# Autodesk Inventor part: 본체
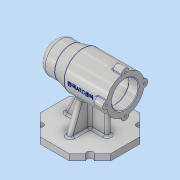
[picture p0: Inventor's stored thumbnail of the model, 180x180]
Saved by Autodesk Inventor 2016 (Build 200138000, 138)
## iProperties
Created: 2019-12
Part Number: 본체
Material: 알루미늄 6061
Document SubType Name: Modeling
Designer: 2-PC10
Density: 2.7 g/cm^3
Appearance: 알루미늄 - 평지
Mass: 724.914 g
Surface Area: 712.64 cm^2
Volume: 268.487 cm^3
Author: 2-PC10
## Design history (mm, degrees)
sketch "스케치1"
  geometry: L1 (0, 0)-(30, 0); L2 (0, 112)-(0, 0); L3 (0, 0)-(30, 0); L4 (30, 0)-(30, 67); L5 (30, 67)-(25, 87); L6 (25, 87)-(25, 112); L7 (25, 112)-(0, 112); L8 (21, 0)-(21, 15); L9 (21, 15)-(21, 15); L10 (24, 18)-(24, 66); L11 (21, 69)-(21, 69); L12 (21, 69)-(21, 80.7); L13 (20.7, 81)-(17.5, 81); L14 (17.5, 81)-(17.5, 98.7); L15 (17.2, 99)-(16, 99); L16 (16, 99)-(16, 102.7); L17 (15.7, 103)-(10.5, 103); L18 (10.5, 103)-(10.5, 103); L19 (7.5, 106)-(0, 106); L20 (21, 0)-(30, 0); A1 r 3 centre (7.5, 103) between (10.5, 103) and (7.5, 106); A2 r 0.3 centre (15.7, 102.7) between (16, 102.7) and (15.7, 103); A3 r 0.3 centre (17.2, 98.7) between (17.5, 98.7) and (17.2, 99); A4 r 0.3 centre (20.7, 80.7) between (21, 80.7) and (20.7, 81); A5 r 3 centre (21, 66) between (24, 66) and (21, 69); A6 r 3 centre (21, 18) between (21, 15) and (24, 18); 4 further points
  constraints: 40 end point, 12 perpendicular, 12 point on circle, 12 tangent, 10 point on line, 6 centre point, 3 equal radius, 3 horizontal, 1 collinear, 1 parallel
  dimensions: "d0" = 112 distance of L2.start L1.start; "d2" = 50 diameter of L6 L2; "d3" = 60 diameter of L4 L2; "d4" = 25 distance of L5.end L6.end; "d5" = 45 distance from line of L7 L4.end; "d7" = 15 distance of L8.start L8.end; "d8" = 54 distance of point (24, 15) point (24, 69); "d9" = 12 distance of L11.end point (21, 81); "d10" = 18 distance of L13.end point (17.5, 99); "d11" = 42 diameter of L8 L2; "d12" = 48 diameter of L10 L2; "d13" = 42 diameter of L12 L2; "d14" = 35 diameter of L14 L2; "d15" = 4 distance between parallel lines of L15 L17; "d16" = 32 diameter of L16 L2; "d17" = 21 diameter of L18 L2; "d18" = 3 distance between parallel lines of L17 L19; "d19" = 3 radius of A1; "d20" = 0.3 radius of A2; "d21" = 3 radius of A5
revolve "회전1" sketch "스케치1" stored, may be unused: angle "d22" = 90 deg
sketch "스케치2"
  geometry: C1 r 6 at (30, 0); 2 further points
  constraints: 1 centre point, 1 horizontal alignment, 1 other
  dimensions: "d23" = 12 diameter of C1
extrude "돌출1" join sketch "스케치2" distance "d24" = 16; taper "d25" = 0 deg
fillet "모깎기1" dims "d26" = 3
fillet "모깎기2" dims "d27" = 1
fillet "모깎기3" dims "d31" = 10
node "작업 평면1"
sketch "스케치3"
  geometry: L1 (6.771, 0)-(29.226, 0) reference; L2 (0, 8)-(0, -5.125); L3 (23.196, 0)-(-23.196, 0); L4 (-56, 32.804)-(-56, 79.196); L5 (-23.196, 112)-(23.196, 112); L6 (56, 79.196)-(56, 32.804); L7 (5.998, 0)-(-5.998, 0) reference; L8 (0, 56)-(67, -11); L9 (56, 32.804)-(43.134, 19.938); L10 (36.062, 12.866)-(23.196, 0); L11 (23.196, 112)-(36.062, 99.134); L12 (43.134, 92.062)-(56, 79.196); L13 (-56, 79.196)-(-43.134, 92.062); L14 (-36.062, 99.134)-(-23.196, 112); L15 (-23.196, 0)-(-36.062, 12.866); L16 (-43.134, 19.938)-(-56, 32.804); A1 r 5 centre (39.598, 16.402) between (43.134, 19.938) and (36.062, 12.866); A2 r 5 centre (39.598, 95.598) between (36.062, 99.134) and (43.134, 92.062); A3 r 5 centre (-39.598, 95.598) between (-43.134, 92.062) and (-36.062, 99.134); A4 r 5 centre (-39.598, 16.402) between (-36.062, 12.866) and (-43.134, 19.938); A5 r 56 centre (0, 56) between (35.908, 98.972) and (-39.598, 16.402); A6 r 56 centre (0, 56) between (-35.908, 13.028) and (42.972, 91.908); 2 further points
  constraints: 28 end point, 16 point on circle, 6 centre point, 2 midpoint, 1 coincident, 1 point on line, 1 vertical, 1 vertical alignment, 26 other
  dimensions: "d37" = 56 distance from line of L1 L8.start; "d40" = 10 diameter of A1; "d43" = 360 deg dimension on L8.start A1.centre (derived)
extrude "돌출2" join sketch "스케치3" distance "d38" = 10; taper "d39" = 0 deg
node "작업 평면2"
sketch "스케치4"
  geometry: L1 (-36, -70)-(-18.584, -22.151); L2 (-56, -80)-(-56, -70) reference; L3 (-56, -70)-(-43.134, -70) reference; L4 (0, 0)-(0, -47); L5 (36, -70)-(18.584, -22.151); L6 (-36.062, -80)-(-36.062, -70) reference; L7 (23.196, -70)-(36.062, -70) reference; L8 (-36.062, -70)-(36.062, -70); A1 r 28.915 centre (0, 0) between (-18.584, -22.151) and (18.584, -22.151); 3 further points
  constraints: 8 end point, 2 point on circle, 2 symmetric about line, 1 centre point, 1 coincident, 1 horizontal, 1 point on line, 1 vertical
  dimensions: "d46" = 20 distance from line of L1.start L2; "d47" = 110 deg angle of L1 L3; "d70" = 28.9147 radius of A1
extrude "돌출3" join sketch "스케치4" stored distance "d49" = 8; taper "d50" = 0 deg
sketch "스케치5"
  geometry: L1 (-70, 99.134)-(-70, 90.598) reference; L2 (-70, 94)-(-25.326, 73.168); L3 (-80, 112)-(-70, 112) reference; L4 (-70, 25)-(-26.997, 25); L5 (-80, 0)-(-70, 0) reference; L6 (-70, 25)-(-70, 94); L7 (-26.997, 25)-(-25.326, 73.168); 3 further points
  constraints: 8 end point, 1 collinear, 1 point on line
  dimensions: "d51" = 115 deg angle of L1 L2; "d52" = 18 distance from line of L2.start L3; "d53" = 25 distance between parallel lines of L4 L5; "d68" = 91.9869 deg angle of L4 L7; "d69" = 43.00307 distance of L4.start L4.end
extrude "돌출4" join sketch "스케치5" stored distance "d54" = 8; taper "d55" = 0 deg
hole "구멍1" diameter "d58" = 3.242; stored, may be unused: countersink angle "d62" = 90 deg, drill point angle "d64" = 118 deg; dims "d56" = 10, "d57" = 10, "d59" = 8, "d60" = 4, "d61" = 2, "d63" = 11
fillet "모깎기4" dims "d71" = 4
chamfer "모따기1" distance "d73" = 1; stored, may be unused: second distance "d74" = 2, angle "d75" = 45 deg
fillet "모깎기6" dims "d76" = 3
node "작업 평면3"
sketch "스케치6"
  geometry: L1 (6.771, 0)-(29.226, 0) reference; 2 further points
  constraints: 1 vertical alignment, 1 other
  dimensions: "d78" = 41 distance from line of L1 point (0, 41)
feature "엠보싱1" sketch "스케치6" dims "d0" = 112, "d2" = 50, "d3" = 60, "d4" = 25, "d5" = 45, "d7" = 15, "d8" = 54, "d9" = 12, "d10" = 18, "d11" = 42, "d12" = 48, "d13" = 42, "d14" = 35, "d15" = 4, "d16" = 32, "d17" = 21, "d18" = 3, "d19" = 3, "d20" = 0.3, "d21" = 3, "d79" = 0.5, "d80" = 0
fillet "모깎기7" dims "d81" = 3
fillet "모깎기8" dims "d82" = 3
node "솔리드1"
pattern_circular "원형 패턴1" dims "d29" = 360 deg
pattern_circular "원형 패턴2" dims angle "d66" = 360 deg
other parameters: "d36" = 112, "d45" = 56, "d48" = 8, "d77" = 53
